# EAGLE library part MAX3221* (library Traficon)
RS-232 Transceivers with AutoShutdown 1µA Supply-Current, True +3V to +5.5V http://dbserv.maxim-ic.com/
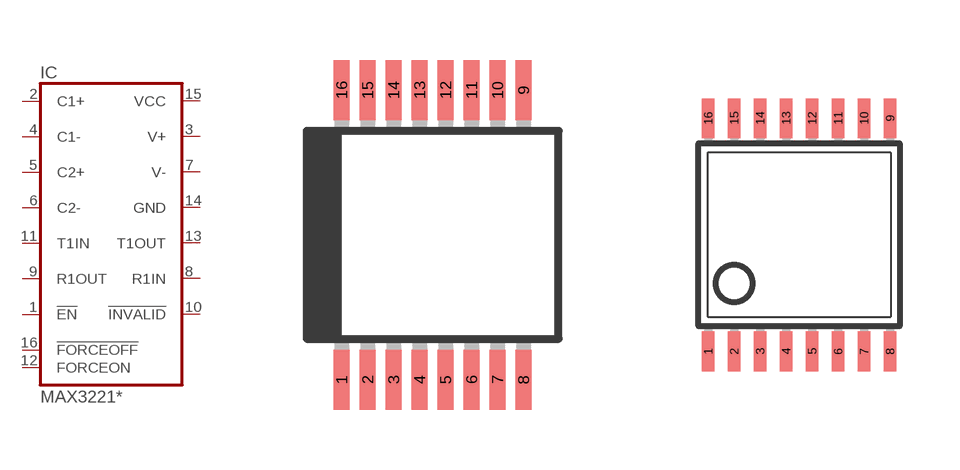
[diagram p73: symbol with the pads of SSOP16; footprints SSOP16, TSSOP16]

Designator prefix IC

## MAX3221CAE, MAX3221EAE  [SSOP16]
1  !EN  in
2  C1+  pas
3  V+  pas
4  C1-  pas
5  C2+  pas
6  C2-  pas
7  V-  pas
8  R1IN  in
9  R1OUT  out
10  !INVALID  out
11  T1IN  in
12  FORCEON  in
13  T1OUT  out
14  GND
15  VCC
16  !FORCEOFF  in

## MAX3221CUE, MAX3221EUE  [TSSOP16]
Pads as for SSOP16

## Footprint SSOP16 (pad centres in mm)
Shrink Small Outline Package package type SS
smd 0.4 x 1.5: 1 -2.275,-3.625; 2 -1.625,-3.625; 3 -0.975,-3.625; 4 -0.325,-3.625; 5 0.325,-3.625; 6 0.975,-3.625; 7 1.625,-3.625; 8 2.275,-3.625; 9 2.275,3.625; 10 1.625,3.625; 11 0.975,3.625; 12 0.325,3.625; 13 -0.325,3.625; 14 -0.975,3.625; 15 -1.625,3.625; 16 -2.275,3.625

## Footprint TSSOP16 (pad centres in mm)
Thin Shrink Small Outline Plastic 16 http://www.maxim-ic.com .. MAX3223-MAX3243.pdf
smd 0.305 x 0.991: 1 -2.275,-2.918; 2 -1.625,-2.918; 3 -0.975,-2.918; 4 -0.325,-2.918; 5 0.325,-2.918; 6 0.975,-2.918; 7 1.625,-2.918; 8 2.275,-2.918; 9 2.275,2.918; 10 1.625,2.918; 11 0.975,2.918; 12 0.325,2.918; 13 -0.325,2.918; 14 -0.975,2.918; 15 -1.625,2.918; 16 -2.275,2.918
